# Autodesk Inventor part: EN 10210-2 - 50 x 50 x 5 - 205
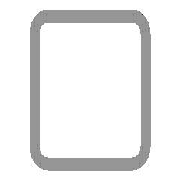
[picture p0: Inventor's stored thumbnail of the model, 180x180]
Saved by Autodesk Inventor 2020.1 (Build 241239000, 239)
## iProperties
_CCFamilyMember: 16
_CCFamilyDisplayName: DIN EN 10210-2 (USAS B17.1 quadratisch) - Rohrleitung — In Klammern angegebene Größen wurden aufgehoben
_FrameMemberDoc: Frame Member File
_Version: 15.0.0
_GetPNFromCC: 1
Created: 2019-01
Part Number: EN 10210-2 - 50 x 50 x 5 - 205
Material: Stahl, weich
Description: Rohrleitung
Document SubType Name: Modeling
Standard: DIN
Designer: lutzd
Standard Revision: 2006-07
Standards Organization: DIN
Language: de-DE
Size Designation: 50 x 50 x 5
Categories: <MemberInstance><Categories><Category DisplayName="Profile" InternalName="089c4875-fa83-4c05-b084-43b9cc11f5ed" Mnemonic="GRDR"><CategoryParameter DisplayName="
Stock Number: 50 x 50 x 5
Mass: 1405.16 g
Surface Area: 711.47 cm^2
Volume: 179.001 cm^3
Density: 7.85 g/cm^3
Appearance: Halbpoliert
Title: Profil-Bauteil
Author: lutzd
Revision Number: -
G_L: 205,000 mm
G_W: 50,000 mm
G_H: 50,000 mm
DocNumber: ADSK-014144
Folder: .
Dimensions: 50x50x205 mm
Mass: 1,405 kg
+BB0DD196-CC0D-47A3-A8DD-34F67BE59085+SCHNITTDETAIL1: Schnittwinkel 90,00 grd
IsCustomPart: 1
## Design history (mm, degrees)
node "Startebene"
node "Endebene"
sketch "Skizze"
  geometry: L1 (-25, -17.5)-(-25, 17.5); L2 (-17.5, 25)-(17.5, 25); L3 (25, 17.5)-(25, -17.5); L4 (17.5, -25)-(-17.5, -25); L5 (-15, 20)-(15, 20); L6 (20, 15)-(20, -15); L7 (15, -20)-(-15, -20); L8 (-20, -15)-(-20, 15); L9 (0, 37.175)-(0, -37.175) reference; L10 (-37.175, 0)-(37.175, 0) reference; A1 r 7.5 centre (-17.5, -17.5) between (-25, -17.5) and (-17.5, -25); A2 r 7.5 centre (-17.5, 17.5) between (-17.5, 25) and (-25, 17.5); A3 r 7.5 centre (17.5, 17.5) between (25, 17.5) and (17.5, 25); A4 r 7.5 centre (17.5, -17.5) between (17.5, -25) and (25, -17.5); A5 r 5 centre (-15, -15) between (-20, -15) and (-15, -20); A6 r 5 centre (-15, 15) between (-15, 20) and (-20, 15); A7 r 5 centre (15, 15) between (20, 15) and (15, 20); A8 r 5 centre (15, -15) between (15, -20) and (20, -15)
  constraints: 16 end point, 16 point on circle, 16 tangent, 8 centre point, 6 equal radius, 4 parallel, 2 perpendicular, 2 other
  dimensions: "d7" = 7.5 radius of A1 (= G_IR); "d10" = 50 distance between parallel lines of L2 L4 (= G_H); "d11" = 50 distance between parallel lines of L1 L3 (= G_W); "d12" = 5 distance between parallel lines of L3 L6 (= G_T); "d15" = 25 distance between parallel lines of L2 L10 (= 0.5 x d10); "d16" = 25 distance between parallel lines of L9 L3 (= 0.5 x d11); "d19" = 5 radius of A5 (= G_T); "d20" = 5 distance between parallel lines of L4 L7 (= G_T)
extrude "Körper" new body sketch "Skizze" stored distance "d3" = 205 (= G_L); taper "d4" = 0 deg
node "Driven Length"
  sketch "Sketch3"
    geometry: L1 (0, 0)-(10, 0) reference
    constraints: 2 end point, 1 horizontal
  workplane "Work Plane3"
  sketch "Sketch4"
    geometry: L1 (-2, 35)-(12, 35) reference; L2 (-2, 240)-(12, 240) reference
    dimensions: "d18" = 205 distance between parallel lines of L1 L2 (derived)
workplane "Arbeitsebene4"
feature "Trennen1"
body "Solid1"
other parameters: "G_W" = 50 [user parameter; used in 1 equation term], "G_H" = 50 [user parameter; used in 1 equation term], "G_T" = 5 [user parameter; used in 3 equation terms], "G_IR" = 7.5 [user parameter; used in 1 equation term], "G_L" = 205 (= d18) [user parameter; used in 1 equation term], "G_OFFSET_START" = -35 [user parameter; used in 1 equation term], "G_OFFSET_END" = 0 [user parameter; used in 1 equation term], "d13" = 35 (= -G_OFFSET_START), "d17" = 90 deg
